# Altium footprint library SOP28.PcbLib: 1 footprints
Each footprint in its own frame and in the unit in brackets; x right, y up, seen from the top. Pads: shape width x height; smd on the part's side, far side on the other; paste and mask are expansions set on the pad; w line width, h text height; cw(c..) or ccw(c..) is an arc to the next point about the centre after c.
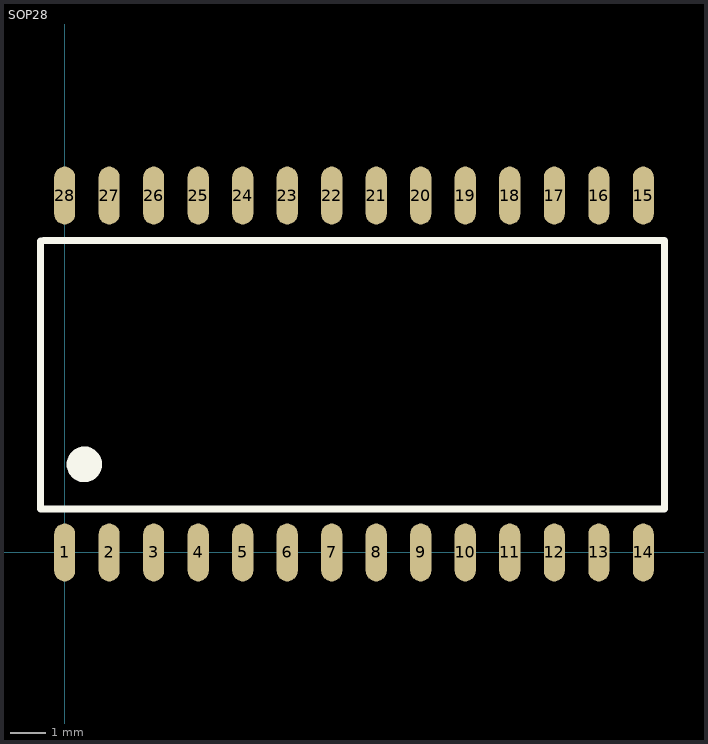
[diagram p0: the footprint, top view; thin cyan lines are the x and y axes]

## SOP28 [mm]
pads (28):
  oval 0.6x1.65 smd: 1(0,0) 2(1.27,0) 3(2.54,0) 4(3.81,0) 5(5.08,0) 6(6.35,0) 7(7.62,0) 8(8.89,0) 9(10.16,0) 10(11.43,0) 11(12.7,0) 12(13.97,0) 13(15.24,0) 14(16.51,0) 15(16.51,10.185) 16(15.24,10.185) 17(13.97,10.185) 18(12.7,10.185) 19(11.43,10.185) 20(10.16,10.185) 21(8.89,10.185) 22(7.62,10.185) 23(6.35,10.185) 24(5.08,10.185) 25(3.81,10.185) 26(2.54,10.185) 27(1.27,10.185) 28(0,10.185)
Top Overlay:
  circle w0.508: c0.559,2.515 r0.254
  lines w0.203: -0.69,8.882 -0.69,1.24 17.111,1.24 17.111,8.903 -0.605,8.903
3D body "SO28.STEP": height 2.64, standoff 0, extent -0.827,-0.199 17.253,10.471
